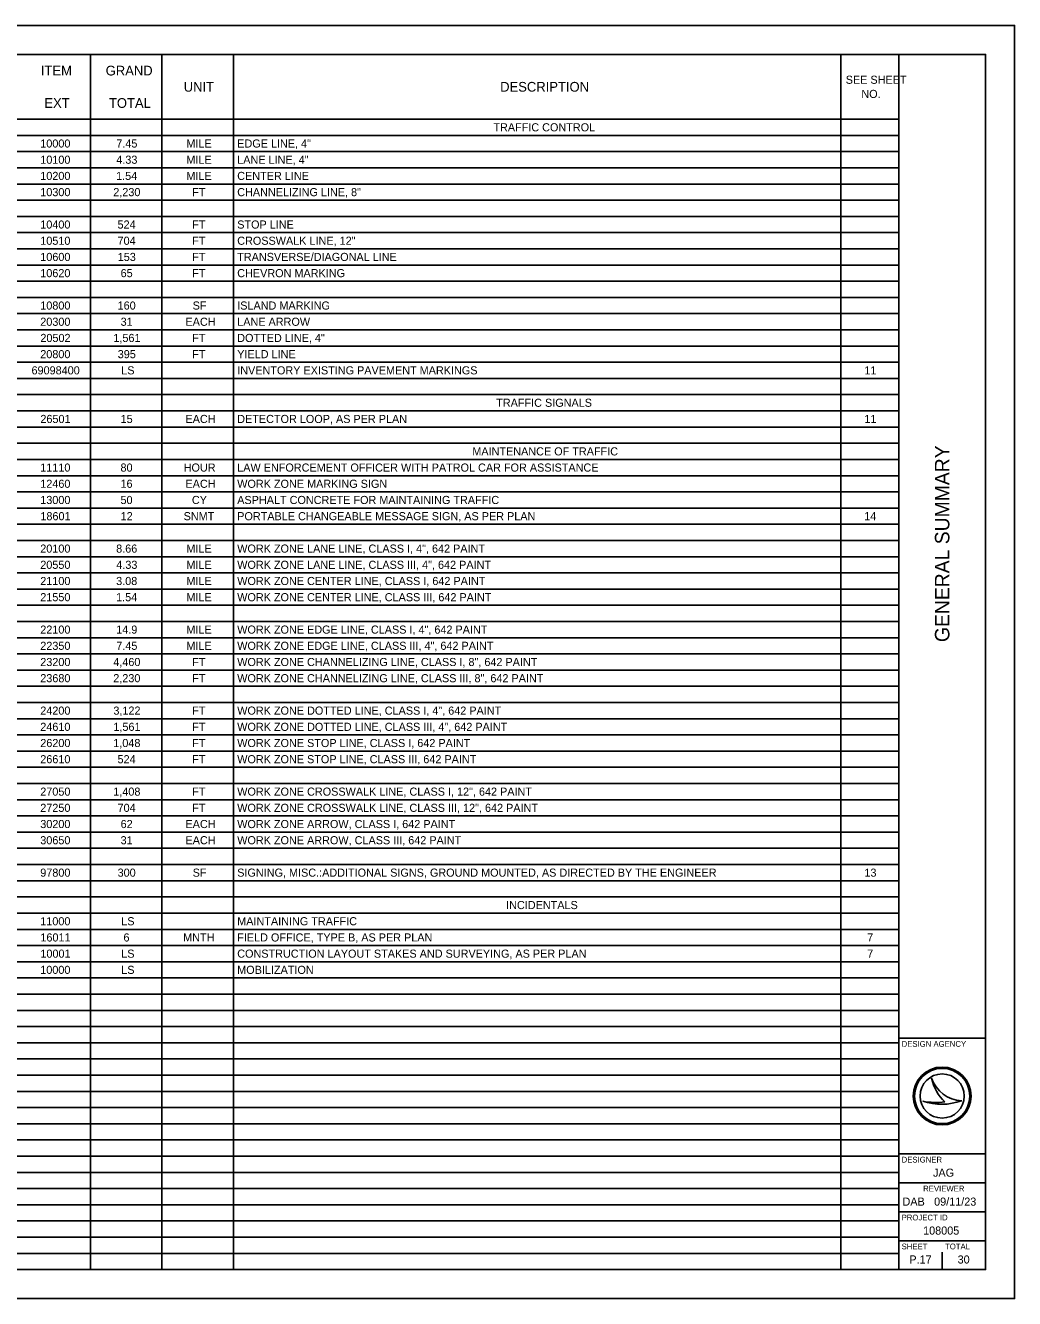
# Model space of a CAD drawing. Extents: x 0 to 34, y 0 to 22.
# Drawn here: x 16.92 to 34, y 0 to 22 of the extents above; entities that cross this region are included whole.
import ezdxf

# ---------------------------------------------------------------- set-up
doc = ezdxf.new("R2010")
doc.units = 0
for name, color, linetype in [('SH_Border', 7, 'Continuous'), ('SH_Cut_Line', 7, 'Continuous'), ('SH_Data', 7, 'Continuous'), ('SH_Text', 7, 'Continuous')]:
    doc.layers.add(name, color=color, linetype=linetype)

msp = doc.modelspace()

# ---------------------------------------------------------------- linework, layer by layer
at = {"layer": 'SH_Border'}
for p, q in [((32, 0.5), (32, 21.5)), ((32, 4.5), (33.5, 4.5)), ((32, 2.5), (33.5, 2.5)), ((32, 2), (33.5, 2)), ((32, 1.5), (33.5, 1.5)), ((32, 1), (33.5, 1))]:
    msp.add_line(p, q, dxfattribs=at)
msp.add_lwpolyline([(1.5, 21.5), (33.5, 21.5), (33.5, 0.5), (1.5, 0.5)], close=True, dxfattribs=at)
at = {"layer": 'SH_Cut_Line'}
msp.add_lwpolyline([(0, 0), (34, 0), (34, 22), (0, 22)], close=True, dxfattribs=at)
at = {"layer": 'SH_Data'}
for p, q in [((32.567, 3.81), (32.567, 3.81)), ((32.417, 3.41), (32.417, 3.41)), ((32.75, 3.5), (32.75, 3.5)), ((33.087, 3.419), (33.087, 3.419)), ((32.375, 0.675), (32.375, 0.675)), ((32.75, 0.5), (32.75, 0.8))]:
    msp.add_line(p, q, dxfattribs=at)
for radius in [0.5, 0.477, 0.477, 0.382]:
    msp.add_circle((32.75, 3.5), radius, dxfattribs=at)
for centre, radius, start, end in [((33.116, 3.998), 0.58, 198.9257, 198.9319), ((33.347, 3.97), 0.796, 191.6379, 191.6421), ((33.116, 3.998), 0.58, 198.9319, 267.1657), ((33.347, 3.97), 0.796, 191.6421, 226.0947), ((32.739, 4.37), 1.013, 251.4576, 290.0832), ((32.648, 4.654), 1.266, 259.4964, 259.4995), ((32.739, 4.37), 1.013, 251.4527, 251.4576), ((32.648, 4.654), 1.266, 259.4995, 276.6672)]:
    msp.add_arc(centre, radius, start, end, dxfattribs=at)
at = {"layer": 'SH_Text'}
for p, q in [((1.5, 21.5), (32.004, 21.5)), ((18.036, 21.5), (18.036, 0.5)), ((19.272, 21.5), (19.272, 0.5)), ((20.507, 21.5), (20.507, 0.5)), ((30.999, 21.5), (30.999, 0.5)), ((32.004, 21.5), (32.004, 0.5)), ((1.5, 20.38), (32.004, 20.38)), ((1.5, 20.1), (32.004, 20.1)), ((1.5, 19.82), (32.004, 19.82)), ((1.5, 19.54), (32.004, 19.54)), ((1.5, 19.26), (32.004, 19.26)), ((1.5, 18.98), (32.004, 18.98)), ((1.5, 18.7), (32.004, 18.7)), ((1.5, 18.42), (32.004, 18.42)), ((1.5, 18.14), (32.004, 18.14)), ((1.5, 17.86), (32.004, 17.86)), ((1.5, 17.58), (32.004, 17.58)), ((1.5, 17.3), (32.004, 17.3)), ((1.5, 17.02), (32.004, 17.02)), ((1.5, 16.74), (32.004, 16.74)), ((1.5, 16.46), (32.004, 16.46)), ((1.5, 16.18), (32.004, 16.18)), ((1.5, 15.9), (32.004, 15.9)), ((1.5, 15.62), (32.004, 15.62)), ((1.5, 15.34), (32.004, 15.34)), ((1.5, 15.06), (32.004, 15.06)), ((1.5, 14.78), (32.004, 14.78)), ((1.5, 14.5), (32.004, 14.5)), ((1.5, 14.22), (32.004, 14.22)), ((1.5, 13.94), (32.004, 13.94)), ((1.5, 13.66), (32.004, 13.66)), ((1.5, 13.38), (32.004, 13.38)), ((1.5, 13.1), (32.004, 13.1)), ((1.5, 12.82), (32.004, 12.82)), ((1.5, 12.54), (32.004, 12.54)), ((1.5, 12.26), (32.004, 12.26)), ((1.5, 11.98), (32.004, 11.98)), ((1.5, 11.7), (32.004, 11.7)), ((1.5, 11.42), (32.004, 11.42)), ((1.5, 11.14), (32.004, 11.14)), ((1.5, 10.86), (32.004, 10.86)), ((1.5, 10.58), (32.004, 10.58)), ((1.5, 10.3), (32.004, 10.3)), ((1.5, 10.02), (32.004, 10.02)), ((1.5, 9.74), (32.004, 9.74)), ((1.5, 9.46), (32.004, 9.46)), ((1.5, 9.18), (32.004, 9.18)), ((1.5, 8.9), (32.004, 8.9)), ((1.5, 8.62), (32.004, 8.62)), ((1.5, 8.34), (32.004, 8.34)), ((1.5, 8.06), (32.004, 8.06)), ((1.5, 7.78), (32.004, 7.78)), ((1.5, 7.5), (32.004, 7.5)), ((1.5, 7.22), (32.004, 7.22)), ((1.5, 6.94), (32.004, 6.94)), ((1.5, 6.66), (32.004, 6.66)), ((1.5, 6.38), (32.004, 6.38)), ((1.5, 6.1), (32.004, 6.1)), ((1.5, 5.82), (32.004, 5.82)), ((1.5, 5.54), (32.004, 5.54)), ((1.5, 5.26), (32.004, 5.26)), ((1.5, 4.98), (32.004, 4.98)), ((1.5, 4.7), (32.004, 4.7)), ((1.5, 4.42), (32.004, 4.42)), ((1.5, 4.14), (32.004, 4.14)), ((1.5, 3.86), (32.004, 3.86)), ((1.5, 3.58), (32.004, 3.58)), ((1.5, 3.3), (32.004, 3.3)), ((1.5, 3.02), (32.004, 3.02)), ((1.5, 2.74), (32.004, 2.74)), ((1.5, 2.46), (32.004, 2.46)), ((1.5, 2.18), (32.004, 2.18)), ((1.5, 1.9), (32.004, 1.9)), ((1.5, 1.62), (32.004, 1.62)), ((1.5, 1.34), (32.004, 1.34)), ((1.5, 1.06), (32.004, 1.06)), ((1.5, 0.78), (32.004, 0.78)), ((1.5, 0.5), (32.004, 0.5))]:
    msp.add_line(p, q, dxfattribs=at)

# ---------------------------------------------------------------- texts
at = {"layer": 'SH_Data'}
msp.add_text('GENERAL SUMMARY', height=0.25, rotation=90, dxfattribs=at).set_placement((32.875, 11.344))
for s, height, p in [('DESIGN AGENCY', 0.1, (32.05, 4.35)), ('DESIGNER', 0.1, (32.05, 2.35)), ('JAG', 0.14, (32.592, 2.105)), ('REVIEWER', 0.1, (32.422, 1.85)), ('DAB', 0.14, (32.065, 1.605)), ('09/11/23', 0.14, (32.611, 1.605)), ('PROJECT ID', 0.1, (32.05, 1.35)), ('108005', 0.14, (32.421, 1.105)), ('SHEET', 0.1, (32.05, 0.85)), ('TOTAL', 0.1, (32.8, 0.85)), ('P.17', 0.14, (32.183, 0.605)), ('30', 0.14, (33.017, 0.605))]:
    msp.add_text(s, height=height, dxfattribs=at).set_placement(p)
at = {"layer": 'SH_Text'}
for s, height, p in [('ITEM', 0.168, (17.181, 21.136)), ('GRAND', 0.168, (18.301, 21.136)), ('SEE SHEET ', 0.14, (31.084, 20.992)), ('UNIT', 0.168, (19.649, 20.856)), ('DESCRIPTION', 0.168, (25.115, 20.856)), ('EXT', 0.168, (17.242, 20.576)), ('TOTAL', 0.168, (18.357, 20.576)), ('NO.', 0.14, (31.354, 20.747)), ('TRAFFIC CONTROL', 0.14, (24.998, 20.17)), ('10000', 0.14, (17.171, 19.89)), ('7.45', 0.14, (18.484, 19.89)), ('MILE', 0.14, (19.695, 19.89)), ('EDGE LINE, 4"', 0.14, (20.573, 19.89)), ('10100', 0.14, (17.171, 19.61)), ('4.33', 0.14, (18.484, 19.61)), ('MILE', 0.14, (19.695, 19.61)), ('LANE LINE, 4"', 0.14, (20.573, 19.61)), ('10200', 0.14, (17.171, 19.33)), ('1.54', 0.14, (18.481, 19.33)), ('MILE', 0.14, (19.695, 19.33)), ('CENTER LINE', 0.14, (20.573, 19.33)), ('10300', 0.14, (17.171, 19.05)), ('2,230', 0.14, (18.432, 19.05)), ('FT', 0.14, (19.796, 19.05)), ('CHANNELIZING LINE, 8"', 0.14, (20.573, 19.05)), ('10400', 0.14, (17.171, 18.49)), ('524', 0.14, (18.506, 18.49)), ('FT', 0.14, (19.796, 18.49)), ('STOP LINE', 0.14, (20.573, 18.49)), ('10510', 0.14, (17.171, 18.21)), ('704', 0.14, (18.506, 18.21)), ('FT', 0.14, (19.796, 18.21)), ('CROSSWALK LINE, 12"', 0.14, (20.573, 18.21)), ('10600', 0.14, (17.171, 17.93)), ('153', 0.14, (18.509, 17.93)), ('FT', 0.14, (19.796, 17.93)), ('TRANSVERSE/DIAGONAL LINE', 0.14, (20.573, 17.93)), ('10620', 0.14, (17.171, 17.65)), ('65', 0.14, (18.559, 17.65)), ('FT', 0.14, (19.796, 17.65)), ('CHEVRON MARKING', 0.14, (20.573, 17.65)), ('10800', 0.14, (17.171, 17.09)), ('160', 0.14, (18.507, 17.09)), ('SF', 0.14, (19.803, 17.09)), ('ISLAND MARKING', 0.14, (20.573, 17.09)), ('20300', 0.14, (17.171, 16.81)), ('31', 0.14, (18.559, 16.81)), ('EACH', 0.14, (19.679, 16.81)), ('LANE ARROW', 0.14, (20.573, 16.81)), ('20502', 0.14, (17.173, 16.53)), ('1,561', 0.14, (18.434, 16.53)), ('FT', 0.14, (19.796, 16.53)), ('DOTTED LINE, 4"', 0.14, (20.573, 16.53)), ('20800', 0.14, (17.171, 16.25)), ('395', 0.14, (18.509, 16.25)), ('FT', 0.14, (19.796, 16.25)), ('YIELD LINE', 0.14, (20.573, 16.25)), ('69098400', 0.14, (17.02, 15.97)), ('LS', 0.14, (18.57, 15.97)), ('INVENTORY EXISTING PAVEMENT MARKINGS', 0.14, (20.573, 15.97)), ('11', 0.14, (31.406, 15.97)), ('TRAFFIC SIGNALS', 0.14, (25.047, 15.41)), ('26501', 0.14, (17.173, 15.13)), ('15', 0.14, (18.559, 15.13)), ('EACH', 0.14, (19.679, 15.13)), ('DETECTOR LOOP, AS PER PLAN', 0.14, (20.573, 15.13)), ('11', 0.14, (31.406, 15.13)), ('MAINTENANCE OF TRAFFIC', 0.14, (24.634, 14.57)), ('11110', 0.14, (17.171, 14.29)), ('80', 0.14, (18.557, 14.29)), ('HOUR', 0.14, (19.648, 14.29)), ('LAW ENFORCEMENT OFFICER WITH PATROL CAR FOR ASSISTANCE', 0.14, (20.573, 14.29)), ('12460', 0.14, (17.171, 14.01)), ('16', 0.14, (18.557, 14.01)), ('EACH', 0.14, (19.679, 14.01)), ('WORK ZONE MARKING SIGN', 0.14, (20.573, 14.01)), ('13000', 0.14, (17.171, 13.73)), ('50', 0.14, (18.557, 13.73)), ('CY', 0.14, (19.79, 13.73)), ('ASPHALT CONCRETE FOR MAINTAINING TRAFFIC', 0.14, (20.573, 13.73)), ('18601', 0.14, (17.173, 13.45)), ('12', 0.14, (18.559, 13.45)), ('SNMT', 0.14, (19.647, 13.45)), ('PORTABLE CHANGEABLE MESSAGE SIGN, AS PER PLAN', 0.14, (20.573, 13.45)), ('14', 0.14, (31.403, 13.45)), ('20100', 0.14, (17.171, 12.89)), ('8.66', 0.14, (18.482, 12.89)), ('MILE', 0.14, (19.695, 12.89)), ('WORK ZONE LANE LINE, CLASS I, 4", 642 PAINT', 0.14, (20.573, 12.89)), ('20550', 0.14, (17.171, 12.61)), ('4.33', 0.14, (18.484, 12.61)), ('MILE', 0.14, (19.695, 12.61)), ('WORK ZONE LANE LINE, CLASS III, 4", 642 PAINT', 0.14, (20.573, 12.61)), ('21100', 0.14, (17.171, 12.33)), ('3.08', 0.14, (18.482, 12.33)), ('MILE', 0.14, (19.695, 12.33)), ('WORK ZONE CENTER LINE, CLASS I, 642 PAINT', 0.14, (20.573, 12.33)), ('21550', 0.14, (17.171, 12.05)), ('1.54', 0.14, (18.481, 12.05)), ('MILE', 0.14, (19.695, 12.05)), ('WORK ZONE CENTER LINE, CLASS III, 642 PAINT', 0.14, (20.573, 12.05)), ('22100', 0.14, (17.171, 11.49)), ('14.9', 0.14, (18.483, 11.49)), ('MILE', 0.14, (19.695, 11.49)), ('WORK ZONE EDGE LINE, CLASS I, 4", 642 PAINT', 0.14, (20.573, 11.49)), ('22350', 0.14, (17.171, 11.21)), ('7.45', 0.14, (18.484, 11.21)), ('MILE', 0.14, (19.695, 11.21)), ('WORK ZONE EDGE LINE, CLASS III, 4", 642 PAINT', 0.14, (20.573, 11.21)), ('23200', 0.14, (17.171, 10.93)), ('4,460', 0.14, (18.432, 10.93)), ('FT', 0.14, (19.796, 10.93)), ('WORK ZONE CHANNELIZING LINE, CLASS I, 8", 642 PAINT', 0.14, (20.573, 10.93)), ('23680', 0.14, (17.171, 10.65)), ('2,230', 0.14, (18.432, 10.65)), ('FT', 0.14, (19.796, 10.65)), ('WORK ZONE CHANNELIZING LINE, CLASS III, 8", 642 PAINT', 0.14, (20.573, 10.65)), ('24200', 0.14, (17.171, 10.09)), ('3,122', 0.14, (18.434, 10.09)), ('FT', 0.14, (19.796, 10.09)), ('WORK ZONE DOTTED LINE, CLASS I, 4", 642 PAINT', 0.14, (20.573, 10.09)), ('24610', 0.14, (17.171, 9.81)), ('1,561', 0.14, (18.434, 9.81)), ('FT', 0.14, (19.796, 9.81)), ('WORK ZONE DOTTED LINE, CLASS III, 4", 642 PAINT', 0.14, (20.573, 9.81)), ('26200', 0.14, (17.171, 9.53)), ('1,048', 0.14, (18.432, 9.53)), ('FT', 0.14, (19.796, 9.53)), ('WORK ZONE STOP LINE, CLASS I, 642 PAINT', 0.14, (20.573, 9.53)), ('26610', 0.14, (17.171, 9.25)), ('524', 0.14, (18.506, 9.25)), ('FT', 0.14, (19.796, 9.25)), ('WORK ZONE STOP LINE, CLASS III, 642 PAINT', 0.14, (20.573, 9.25)), ('27050', 0.14, (17.171, 8.69)), ('1,408', 0.14, (18.432, 8.69)), ('FT', 0.14, (19.796, 8.69)), ('WORK ZONE CROSSWALK LINE, CLASS I, 12", 642 PAINT', 0.14, (20.573, 8.69)), ('27250', 0.14, (17.171, 8.41)), ('704', 0.14, (18.506, 8.41)), ('FT', 0.14, (19.796, 8.41)), ('WORK ZONE CROSSWALK LINE, CLASS III, 12", 642 PAINT', 0.14, (20.573, 8.41)), ('30200', 0.14, (17.171, 8.13)), ('62', 0.14, (18.559, 8.13)), ('EACH', 0.14, (19.679, 8.13)), ('WORK ZONE ARROW, CLASS I, 642 PAINT', 0.14, (20.573, 8.13)), ('30650', 0.14, (17.171, 7.85)), ('31', 0.14, (18.559, 7.85)), ('EACH', 0.14, (19.679, 7.85)), ('WORK ZONE ARROW, CLASS III, 642 PAINT', 0.14, (20.573, 7.85)), ('97800', 0.14, (17.171, 7.29)), ('300', 0.14, (18.507, 7.29)), ('SF', 0.14, (19.803, 7.29)), ('SIGNING, MISC.:ADDITIONAL SIGNS, GROUND MOUNTED, AS DIRECTED BY THE ENGINEER', 0.14, (20.573, 7.29)), ('13', 0.14, (31.407, 7.29)), ('INCIDENTALS', 0.14, (25.218, 6.73)), ('11000', 0.14, (17.171, 6.45)), ('LS', 0.14, (18.57, 6.45)), ('MAINTAINING TRAFFIC', 0.14, (20.573, 6.45)), ('16011', 0.14, (17.173, 6.17)), ('6', 0.14, (18.608, 6.17)), ('MNTH', 0.14, (19.639, 6.17)), ('FIELD OFFICE, TYPE B, AS PER PLAN', 0.14, (20.573, 6.17)), ('7', 0.14, (31.455, 6.17)), ('10001', 0.14, (17.173, 5.89)), ('LS', 0.14, (18.57, 5.89)), ('CONSTRUCTION LAYOUT STAKES AND SURVEYING, AS PER PLAN', 0.14, (20.573, 5.89)), ('7', 0.14, (31.455, 5.89)), ('10000', 0.14, (17.171, 5.61)), ('LS', 0.14, (18.57, 5.61)), ('MOBILIZATION', 0.14, (20.573, 5.61))]:
    msp.add_text(s, height=height, dxfattribs=at).set_placement(p)

doc.saveas('drawing.dxf')
